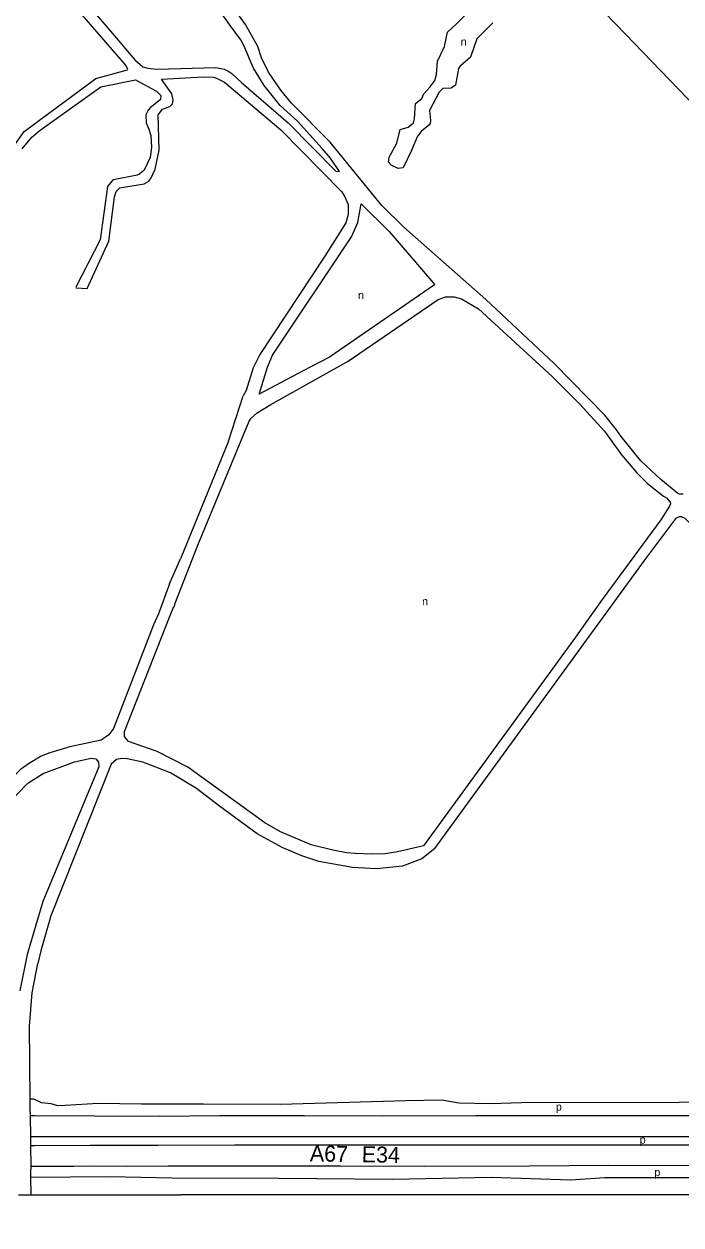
# Model space of a CAD drawing. Extents: x 162667 to 164645, y 379003 to 382150.
# Drawn here: x 163924 to 164252, y 379500 to 380100 of the extents above; entities that cross this region are included whole.
import ezdxf

# ---------------------------------------------------------------- set-up
doc = ezdxf.new("R2010")
doc.units = 0
for name, color, linetype in [('BLT_Basislijn', 7, 'Continuous'), ('BLT_Centroide', 7, 'Continuous'), ('BLT_Gemeentegrens', 7, 'Continuous'), ('BLT_Straatnaam_hoofdweg', 7, 'Continuous')]:
    doc.layers.add(name, color=color, linetype=linetype)

msp = doc.modelspace()

# ---------------------------------------------------------------- linework, layer by layer
at = {"layer": 'BLT_Basislijn'}
for p, q in [((164085.81, 379931.69), (164130.84, 379962.43)), ((164130.84, 379962.43), (164134.44, 379963.78)), ((164134.44, 379963.78), (164138.68, 379963.86)), ((164138.68, 379963.86), (164142.34, 379962.84)), ((164142.34, 379962.84), (164150.84, 379957.81)), ((164150.84, 379957.81), (164187.7, 379924.05)), ((164047.08, 379910.03), (164085.81, 379931.69)), ((164187.7, 379924.05), (164201.5, 379910.21)), ((164025.99, 379891.62), (164033.29, 379914.35)), ((164037.4, 379903.22), (164040.26, 379905.8)), ((164040.26, 379905.8), (164047.08, 379910.03)), ((164201.5, 379910.21), (164213.91, 379896.66)), ((164010.74, 379839.71), (164036.25, 379901.69)), ((164036.25, 379901.69), (164037.4, 379903.22)), ((164213.91, 379896.66), (164222.35, 379884.87)), ((164025.99, 379891.62), (164002.04, 379832.96)), ((164222.35, 379884.87), (164229.99, 379875.95)), ((164229.99, 379875.95), (164235.41, 379870.6)), ((164235.41, 379870.6), (164243.37, 379864.17)), ((164243.37, 379864.17), (164244.8, 379863.31)), ((164246.41, 379859.18), (164241.93, 379852.38)), ((164244.8, 379863.31), (164246.62, 379861.21)), ((164246.78, 379860.35), (164246.41, 379859.18)), ((164246.62, 379861.21), (164246.78, 379860.35)), ((164241.93, 379852.38), (164212.77, 379812.63)), ((163999.33, 379810.78), (164010.74, 379839.71)), ((163996.53, 379820.38), (164002.04, 379832.96)), ((163998.95, 379809.09), (163999.33, 379810.78)), ((164212.77, 379812.63), (164199.38, 379793.82)), ((163974.11, 379746.61), (163996.51, 379803.75)), ((163996.51, 379803.75), (163998.67, 379809.12)), ((163998.67, 379809.12), (163998.95, 379809.09)), ((164199.38, 379793.82), (164123.42, 379689.52)), ((163974.08, 379744.09), (163974.11, 379746.61)), ((163976.05, 379741.55), (163974.08, 379744.09)), ((163990.42, 379736.61), (163976.05, 379741.55)), ((164005.61, 379728.74), (163990.42, 379736.61)), ((164044.21, 379700.94), (164005.61, 379728.74)), ((164052.01, 379696.48), (164044.21, 379700.94)), ((164067.24, 379689.92), (164052.01, 379696.48)), ((164078.08, 379687.34), (164067.24, 379689.92)), ((164084.92, 379686.05), (164078.08, 379687.34)), ((164089.44, 379685.57), (164084.92, 379686.05)), ((164097.22, 379685.34), (164089.44, 379685.57)), ((164104.12, 379685.49), (164097.22, 379685.34)), ((164109.63, 379686.39), (164104.12, 379685.49)), ((164113.52, 379687.08), (164109.63, 379686.39)), ((164123.42, 379689.52), (164113.52, 379687.08)), ((163932.32, 379637.01), (163930.78, 379630.59)), ((163926.98, 379556.31), (163926.92, 379562.81)), ((163926.98, 379556.31), (163926.99, 379554.6)), ((163926.99, 379554.6), (163927.04, 379544.07)), ((163927.04, 379544.07), (163927.05, 379541.97)), ((163927.05, 379541.97), (163927.07, 379539.76)), ((163927.07, 379539.76), (163927.19, 379529.39)), ((163927.19, 379529.39), (163927.21, 379527.81)), ((163927.26, 379523.9), (163927.21, 379527.81)), ((163927.36, 379515.11), (163927.26, 379523.9))]:
    msp.add_line(p, q, dxfattribs=at)
for points in [[(164253.18, 379865.24), (164251.27, 379865.25), (164250.47, 379865.54), (164241.98, 379872.47), (164232.06, 379881.85), (164222.18, 379894.03), (164219.91, 379897.37), (164214.07, 379904.62), (164188.75, 379930.58), (164154.51, 379962.43), (164113.66, 379998.64), (164102.62, 380009.44), (164076.84, 380041.18), (164057.52, 380060.54), (164052.11, 380067.05), (164046.06, 380076.13), (164042.55, 380083.23), (164040.58, 380088.97), (164034.58, 380100), (164013.48, 380129.07)], [(164273.49, 380044.64), (164259.9, 380058.22), (164219.64, 380100), (164200.33, 380119.99)], [(163957.13, 380100), (163953.1, 380104.62)], [(163956.12, 380109.25), (163964.26, 380100), (163979.13, 380082.25), (163983.22, 380078.84), (163985.7, 380078.07), (163990.23, 380077.68), (164019.69, 380078.52), (164023.76, 380077.63), (164026.15, 380076.45), (164027.71, 380075.42), (164032.55, 380070.87), (164055.84, 380050.81), (164079.63, 380026.58), (164081.42, 380026.46)], [(164081.42, 380026.46), (164077.02, 380033.12), (164072.84, 380037.92), (164060.4, 380051.54), (164051.79, 380059.49), (164043.83, 380069.36), (164038.57, 380078.04), (164033.63, 380089.39), (164032.09, 380092.28), (164026.52, 380100), (164022.34, 380105.83)], [(164158.01, 380100.71), (164157.31, 380100), (164150.05, 380092.79), (164146.93, 380083.55), (164141.83, 380079.09), (164140.97, 380077.88), (164139.38, 380069.6), (164137.31, 380068.04), (164133.17, 380067.98), (164131.26, 380066.18), (164126.48, 380057.02), (164126.96, 380051.92), (164126.8, 380050.4), (164126.16, 380049.54), (164122.2, 380046.4), (164120.42, 380044.18), (164117.2, 380036.6), (164113.26, 380028.36), (164110.78, 380028.04), (164107.21, 380029.63), (164106, 380031.13), (164106.32, 380033.71), (164110.08, 380040.62), (164111.81, 380047.52), (164115.73, 380048.55), (164118.4, 380050.73), (164118.89, 380052.85), (164119.36, 380060.4), (164122.59, 380062.98), (164123.58, 380065.3), (164126.58, 380068.54), (164129.03, 380071.99), (164129.98, 380074.86), (164130.46, 380081.55), (164133.96, 380088.97), (164135.38, 380096.16), (164139.51, 380100), (164145.68, 380106.01)], [(163911.36, 380029.01), (163923.91, 380046.51), (163959.78, 380072.93), (163975.59, 380077.21), (163975.71, 380077.65), (163974.49, 380079.73), (163957.13, 380100)], [(163922.86, 380037.85), (163927.8, 380043.58), (163931.94, 380047.08), (163962.2, 380068.7), (163979.56, 380072.28), (163990.08, 380066.53), (163992.17, 380064.44), (163991.99, 380062.43), (163986.89, 380058.29), (163985.86, 380057.18), (163984.75, 380054.79), (163984.84, 380050.81), (163986.27, 380047.69), (163987.26, 380044.41), (163987.61, 380038.68), (163986.82, 380033.52), (163983.95, 380027.2), (163981.5, 380025.08), (163980.38, 380024.6), (163968.6, 380022.26), (163967.8, 380021.73), (163965.48, 380019.05), (163961.97, 379992.27), (163949.77, 379968.64), (163949.85, 379968.35), (163955.33, 379967.96), (163966.18, 379991.73), (163968.98, 380013.86), (163969.85, 380016.53), (163971.75, 380018.26), (163983.95, 380020.35), (163986.18, 380021.67), (163987.31, 380023.22), (163989.33, 380027.7), (163991.43, 380037.11), (163990.8, 380054.79), (163993.03, 380057.55), (163996.69, 380058.87), (163997.96, 380060.36), (163998.44, 380062.08), (163997.65, 380065.23), (163992.45, 380072.56), (164013.41, 380073.82), (164018.44, 380073.54), (164020.09, 380073.14), (164024.05, 380071.12), (164052.09, 380047.21), (164082.51, 380016.51), (164083.91, 380014.21), (164085.71, 380010.04), (164085.82, 380004.98), (164084.7, 380000.76), (164074.08, 379984.09), (164041.6, 379934.97), (164038.41, 379928.28), (164034.91, 379916.94), (164033.29, 379914.35)], [(164063.03, 379926.61), (164041.28, 379915.13), (164045.42, 379928.76), (164048.03, 379934.65), (164087.46, 379993.89), (164090.65, 380000.96), (164092.34, 380010.26), (164106.3, 379996.52), (164128.39, 379970.73), (164128.93, 379969.75), (164076.47, 379933.76), (164063.03, 379926.61)], [(164129.1, 379688.15), (164233.8, 379832.11), (164249.9, 379853.42), (164251.27, 379853.98), (164252.22, 379854.01), (164254.04, 379853.24), (164293.57, 379813.71), (164382.22, 379722.34), (164453.26, 379664.15), (164503.02, 379633.75), (164513.04, 379627.11), (164531.31, 379616.03)], [(163996.53, 379820.38), (163990.95, 379805.46), (163988.54, 379799.88), (163968.5, 379748.14), (163966.27, 379744.89), (163962.45, 379742.34), (163946.71, 379739.02), (163936.81, 379735.91), (163932.45, 379734.32), (163926.1, 379730.49), (163922.06, 379727.54), (163919.52, 379725.09), (163911.08, 379715.59), (163903.85, 379709.7), (163896.27, 379705.49)], [(163914.74, 379709.38), (163924.69, 379719.78), (163926.28, 379721.1), (163933.47, 379725.56), (163949.07, 379731.41), (163957.45, 379733.35), (163959.71, 379733.03), (163961.11, 379731.21), (163961.18, 379729.03), (163933.31, 379661.7), (163925.35, 379635.17), (163921.79, 379616.95)], [(164129.1, 379688.15), (164122.66, 379683.01), (164112.96, 379679.31), (164099.88, 379678.01), (164087.9, 379678.57), (164071.15, 379681.67), (164062.71, 379684.53), (164052.9, 379688.68), (164040.33, 379695.52), (164021.48, 379709.29), (164009.96, 379718.19), (163996.95, 379725.93), (163983.25, 379731.31), (163975.41, 379733.03), (163972.78, 379733.05), (163970.03, 379732.68), (163967.43, 379730.27), (163937.29, 379654.44), (163932.32, 379637.01)], [(163926.92, 379562.81), (163926.54, 379599.3), (163927.93, 379616.03), (163930.78, 379630.59)], [(163944.47, 379559.73), (163940.69, 379559.54), (163937.45, 379560.51), (163932.59, 379561), (163928.7, 379562.95), (163926.92, 379562.81)], [(164546.67, 379560.8), (164507.89, 379560.68), (164486.31, 379561.44), (164471.04, 379562.61), (164448.71, 379562.82), (164426.63, 379562.69), (164387.84, 379562.4), (164372.43, 379562.88), (164366.35, 379561.32), (164306.77, 379561.67), (164251.21, 379561.28), (164172.45, 379561.01), (164156.9, 379560.56), (164141.1, 379560.87), (164132.66, 379562.43), (164114.59, 379562.04), (164052, 379560.28), (164013.58, 379560.33), (163982.52, 379560.44), (163960.82, 379560.64), (163944.47, 379559.73)], [(164021.49, 379554.47), (163991.74, 379554.27), (163959.15, 379554.33), (163929.22, 379554.62), (163926.99, 379554.6)], [(164398.86, 379554.49), (164355.65, 379554.56), (164312.1, 379554.49), (164276.94, 379554.54), (164232.94, 379554.55), (164192.55, 379554.53), (164149.47, 379554.61), (164102.89, 379554.45), (164063.99, 379554.5), (164021.49, 379554.47)], [(164029.45, 379544.02), (163993.67, 379543.98), (163952.98, 379544.05), (163929.22, 379544.07), (163927.04, 379544.07)], [(163927.07, 379539.76), (163929.22, 379539.76), (163956.82, 379539.81), (163990.91, 379539.9), (164029.22, 379539.98)], [(164029.22, 379539.98), (164060.73, 379539.99), (164097.62, 379540.02), (164137.31, 379540.04), (164177.07, 379540.01), (164211.09, 379539.99), (164249.96, 379540.01), (164290.51, 379540.06), (164328, 379540.09), (164366.17, 379540.09), (164399.4, 379540.09)], [(164398.86, 379544.1), (164348.88, 379544.07), (164310.76, 379544.05), (164272.24, 379544.1), (164231.23, 379544.09), (164187.82, 379544.07), (164154.65, 379544.06), (164118.59, 379544.02), (164079.03, 379544.02), (164029.45, 379544.02)], [(163927.19, 379529.39), (163929.22, 379529.43), (163948.64, 379529.42), (163957.1, 379529.49), (163974.99, 379529.45), (163995.86, 379529.5), (164029.71, 379529.5)], [(164029.71, 379529.5), (164081.97, 379529.52), (164123.93, 379529.45), (164176.4, 379529.59), (164215.93, 379529.84), (164264.56, 379529.71), (164311.18, 379529.79), (164353.87, 379529.81), (164399.36, 379529.77)], [(163927.26, 379523.9), (163966.78, 379524.17), (163997.61, 379523.61), (164050.96, 379523.37), (164108.17, 379522.87), (164157.22, 379523.82), (164196.88, 379522.6), (164214.02, 379523.67), (164266.47, 379523.66), (164305.22, 379523.86), (164334.32, 379523.93), (164380.28, 379522.72), (164416.11, 379522.98), (164430.58, 379523.6), (164440.87, 379522.99), (164453.22, 379521.36), (164467.46, 379518.33), (164482.3, 379514.66), (164509.68, 379507.89), (164521.4, 379505.55)], [(163967.36, 379515.09), (163967.35, 379515.12)], [(163973.8, 379515.12), (163973.81, 379515.09)], [(163994.97, 379515.09), (163994.99, 379515.12)], [(164002.06, 379515.09), (164002.08, 379515.12)], [(164096.68, 379515.1), (164096.68, 379515.08)]]:
    msp.add_lwpolyline(points, dxfattribs=at)
at = {"layer": 'BLT_Gemeentegrens'}
for p, q in [((163921.15, 379515.11), (163927.36, 379515.11)), ((163927.36, 379515.11), (163967.35, 379515.12)), ((163967.35, 379515.12), (163973.8, 379515.12)), ((163973.8, 379515.12), (163994.99, 379515.12)), ((164096.68, 379515.1), (164002.08, 379515.12))]:
    msp.add_line(p, q, dxfattribs=at)
for points in [[(163994.99, 379515.12), (164000, 379515.12), (164002.08, 379515.12)], [(164498.81, 379500), (164408.36, 379515.05), (164096.68, 379515.1)]]:
    msp.add_lwpolyline(points, dxfattribs=at)

# ---------------------------------------------------------------- texts
at = {"layer": 'BLT_Centroide'}
for s, p in [('n', (164142.03, 380089.33)), ('n', (164090.75, 379962.67)), ('n', (164122.73, 379809.67)), ('p', (164189.56, 379557.1)), ('p', (164231.46, 379540.64)), ('p', (164238.77, 379524.38))]:
    msp.add_text(s, height=4, dxfattribs=at).set_placement(p)
at = {"layer": 'BLT_Straatnaam_hoofdweg'}
for s, p in [('A67', (164066.62, 379531.85)), ('E34', (164092.52, 379531.39))]:
    msp.add_text(s, height=8, rotation=358.8479, dxfattribs=at).set_placement(p)

doc.saveas('drawing.dxf')
